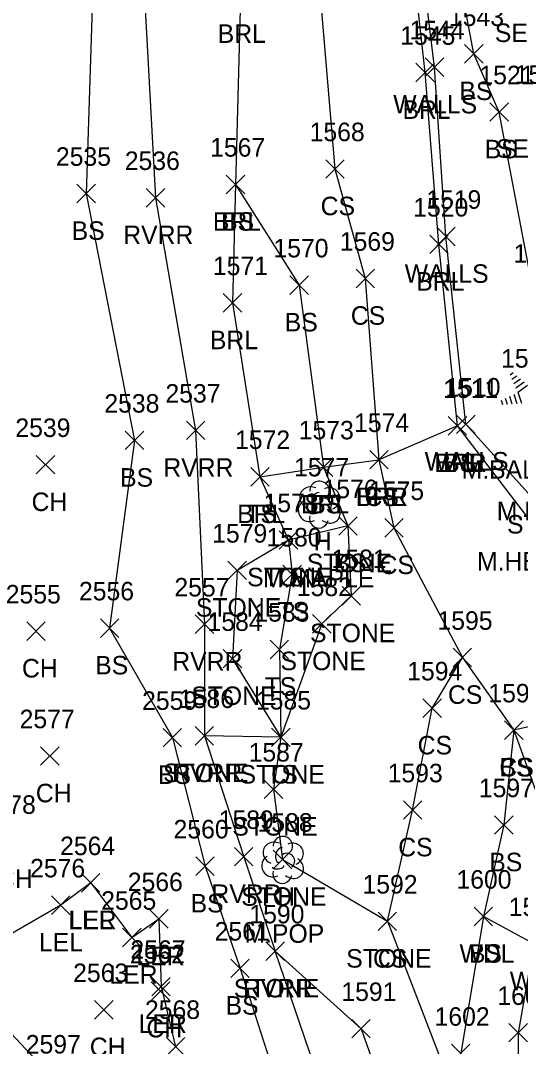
# Model space of a CAD drawing. Extents: x 1512665 to 1513714, y 110636 to 112816.
# Drawn here: x 1513047.2 to 1513101.2, y 110908.3 to 111019.1 of the extents above; entities that cross this region are included whole.
import ezdxf

# ---------------------------------------------------------------- set-up
doc = ezdxf.new("R2010")
doc.units = 0
for name, color, linetype in [('L_A', 7, 'Continuous'), ('L_C', 7, 'Continuous'), ('L_I', 7, 'Continuous'), ('L_TIC', 7, 'Continuous'), ('LABL', 7, 'Continuous'), ('LARO', 7, 'Continuous'), ('LASF', 7, 'Continuous'), ('LAWA', 7, 'Continuous'), ('LAWE', 7, 'Continuous'), ('LELB', 7, 'Continuous'), ('LTC', 7, 'Continuous'), ('LTD', 7, 'Continuous'), ('LWS', 7, 'Continuous'), ('U_A', 7, 'Continuous'), ('U_I', 7, 'Continuous')]:
    doc.layers.add(name, color=color, linetype=linetype)

msp = doc.modelspace()

# ---------------------------------------------------------------- linework, layer by layer
at = {"layer": 'L_TIC'}
for points in [[(1513095.17, 111014.48), (1513097.17, 111016.48)], [(1513097.17, 111014.48), (1513095.17, 111016.48)], [(1513089.91, 111012.45), (1513091.91, 111014.45)], [(1513091.91, 111012.45), (1513089.91, 111014.45)], [(1513090.91, 111013.04), (1513092.91, 111015.04)], [(1513092.91, 111013.04), (1513090.91, 111015.04)], [(1513097.9, 111008.19), (1513099.9, 111010.19)], [(1513099.9, 111008.19), (1513097.9, 111010.19)], [(1513080.17, 111002.04), (1513082.17, 111004.04)], [(1513082.17, 111002.04), (1513080.17, 111004.04)], [(1513069.42, 111000.37), (1513071.42, 111002.37)], [(1513071.42, 111000.37), (1513069.42, 111002.37)], [(1513069.42, 111000.37), (1513071.42, 111002.37)], [(1513071.42, 111000.37), (1513069.42, 111002.37)], [(1513053.28, 110999.38), (1513055.28, 111001.38)], [(1513055.28, 110999.38), (1513053.28, 111001.38)], [(1513060.78, 110998.93), (1513062.78, 111000.93)], [(1513062.78, 110998.93), (1513060.78, 111000.93)], [(1513092.16, 110994.74), (1513094.16, 110996.74)], [(1513094.16, 110994.74), (1513092.16, 110996.74)], [(1513091.4, 110993.9), (1513093.4, 110995.9)], [(1513093.4, 110993.9), (1513091.4, 110995.9)], [(1513083.44, 110990.21), (1513085.44, 110992.21)], [(1513085.44, 110990.21), (1513083.44, 110992.21)], [(1513076.29, 110989.49), (1513078.29, 110991.49)], [(1513078.29, 110989.49), (1513076.29, 110991.49)], [(1513069.1, 110987.57), (1513071.1, 110989.57)], [(1513071.1, 110987.57), (1513069.1, 110989.57)], [(1513094.31, 110974.46), (1513096.31, 110976.46)], [(1513096.31, 110974.46), (1513094.31, 110976.46)], [(1513065.11, 110973.8), (1513067.11, 110975.8)], [(1513067.11, 110973.8), (1513065.11, 110975.8)], [(1513093.41, 110974.3), (1513095.41, 110976.3)], [(1513095.41, 110974.3), (1513093.41, 110976.3)], [(1513093.41, 110974.3), (1513095.41, 110976.3)], [(1513095.41, 110974.3), (1513093.41, 110976.3)], [(1513093.41, 110974.3), (1513095.41, 110976.3)], [(1513095.41, 110974.3), (1513093.41, 110976.3)], [(1513058.51, 110972.72), (1513060.51, 110974.72)], [(1513060.51, 110972.72), (1513058.51, 110974.72)], [(1513048.9, 110970.09), (1513050.9, 110972.09)], [(1513050.9, 110970.09), (1513048.9, 110972.09)], [(1513084.92, 110970.63), (1513086.92, 110972.63)], [(1513086.92, 110970.63), (1513084.92, 110972.63)], [(1513084.92, 110970.63), (1513086.92, 110972.63)], [(1513086.92, 110970.63), (1513084.92, 110972.63)], [(1513084.92, 110970.63), (1513086.92, 110972.63)], [(1513086.92, 110970.63), (1513084.92, 110972.63)], [(1513078.94, 110969.83), (1513080.94, 110971.83)], [(1513080.94, 110969.83), (1513078.94, 110971.83)], [(1513078.94, 110969.83), (1513080.94, 110971.83)], [(1513080.94, 110969.83), (1513078.94, 110971.83)], [(1513072.06, 110968.79), (1513074.06, 110970.79)], [(1513074.06, 110968.79), (1513072.06, 110970.79)], [(1513072.06, 110968.79), (1513074.06, 110970.79)], [(1513074.06, 110968.79), (1513072.06, 110970.79)], [(1513081.57, 110963.48), (1513083.57, 110965.48)], [(1513083.57, 110963.48), (1513081.57, 110965.48)], [(1513081.57, 110963.48), (1513083.57, 110965.48)], [(1513083.57, 110963.48), (1513081.57, 110965.48)], [(1513081.57, 110963.48), (1513083.57, 110965.48)], [(1513083.57, 110963.48), (1513081.57, 110965.48)], [(1513086.54, 110963.28), (1513088.54, 110965.28)], [(1513088.54, 110963.28), (1513086.54, 110965.28)], [(1513075.14, 110961.96), (1513077.14, 110963.96)], [(1513077.14, 110961.96), (1513075.14, 110963.96)], [(1513075.14, 110961.96), (1513077.14, 110963.96)], [(1513077.14, 110961.96), (1513075.14, 110963.96)], [(1513069.6, 110958.68), (1513071.6, 110960.68)], [(1513071.6, 110958.68), (1513069.6, 110960.68)], [(1513075.55, 110958.26), (1513077.55, 110960.26)], [(1513077.55, 110958.26), (1513075.55, 110960.26)], [(1513081.93, 110955.92), (1513083.93, 110957.92)], [(1513083.93, 110955.92), (1513081.93, 110957.92)], [(1513055.82, 110952.44), (1513057.82, 110954.44)], [(1513057.82, 110952.44), (1513055.82, 110954.44)], [(1513066.08, 110952.86), (1513068.08, 110954.86)], [(1513068.08, 110952.86), (1513066.08, 110954.86)], [(1513078.74, 110952.9), (1513080.74, 110954.9)], [(1513080.74, 110952.9), (1513078.74, 110954.9)], [(1513047.86, 110952.11), (1513049.86, 110954.11)], [(1513049.86, 110952.11), (1513047.86, 110954.11)], [(1513074.16, 110950.14), (1513076.16, 110952.14)], [(1513076.16, 110950.14), (1513074.16, 110952.14)], [(1513069.1, 110949.14), (1513071.1, 110951.14)], [(1513071.1, 110949.14), (1513069.1, 110951.14)], [(1513093.93, 110949.26), (1513095.93, 110951.26)], [(1513095.93, 110949.26), (1513093.93, 110951.26)], [(1513093.93, 110949.26), (1513095.93, 110951.26)], [(1513095.93, 110949.26), (1513093.93, 110951.26)], [(1513090.66, 110943.8), (1513092.66, 110945.8)], [(1513092.66, 110943.8), (1513090.66, 110945.8)], [(1513099.49, 110941.42), (1513101.49, 110943.42)], [(1513101.49, 110941.42), (1513099.49, 110943.42)], [(1513099.49, 110941.42), (1513101.49, 110943.42)], [(1513101.49, 110941.42), (1513099.49, 110943.42)], [(1513062.6, 110940.61), (1513064.6, 110942.61)], [(1513064.6, 110940.61), (1513062.6, 110942.61)], [(1513066.06, 110940.81), (1513068.06, 110942.81)], [(1513068.06, 110940.81), (1513066.06, 110942.81)], [(1513066.06, 110940.81), (1513068.06, 110942.81)], [(1513068.06, 110940.81), (1513066.06, 110942.81)], [(1513074.32, 110940.65), (1513076.32, 110942.65)], [(1513076.32, 110940.65), (1513074.32, 110942.65)], [(1513074.32, 110940.65), (1513076.32, 110942.65)], [(1513076.32, 110940.65), (1513074.32, 110942.65)], [(1513074.32, 110940.65), (1513076.32, 110942.65)], [(1513076.32, 110940.65), (1513074.32, 110942.65)], [(1513049.36, 110938.63), (1513051.36, 110940.63)], [(1513051.36, 110938.63), (1513049.36, 110940.63)], [(1513073.53, 110935.03), (1513075.53, 110937.03)], [(1513075.53, 110935.03), (1513073.53, 110937.03)], [(1513088.56, 110932.79), (1513090.56, 110934.79)], [(1513090.56, 110932.79), (1513088.56, 110934.79)], [(1513098.4, 110931.18), (1513100.4, 110933.18)], [(1513100.4, 110931.18), (1513098.4, 110933.18)], [(1513070.31, 110927.75), (1513072.31, 110929.75)], [(1513072.31, 110927.75), (1513070.31, 110929.75)], [(1513074.49, 110927.45), (1513076.49, 110929.45)], [(1513076.49, 110927.45), (1513074.49, 110929.45)], [(1513066.13, 110926.73), (1513068.13, 110928.73)], [(1513068.13, 110926.73), (1513066.13, 110928.73)], [(1513053.78, 110924.92), (1513055.78, 110926.92)], [(1513055.78, 110924.92), (1513053.78, 110926.92)], [(1513053.78, 110924.92), (1513055.78, 110926.92)], [(1513055.78, 110924.92), (1513053.78, 110926.92)], [(1513050.54, 110922.52), (1513052.54, 110924.52)], [(1513052.54, 110922.52), (1513050.54, 110924.52)], [(1513096.2, 110921.3), (1513098.2, 110923.3)], [(1513098.2, 110921.3), (1513096.2, 110923.3)], [(1513096.2, 110921.3), (1513098.2, 110923.3)], [(1513098.2, 110921.3), (1513096.2, 110923.3)], [(1513061.14, 110921.03), (1513063.14, 110923.03)], [(1513063.14, 110921.03), (1513061.14, 110923.03)], [(1513085.83, 110920.77), (1513087.83, 110922.77)], [(1513087.83, 110920.77), (1513085.83, 110922.77)], [(1513085.83, 110920.77), (1513087.83, 110922.77)], [(1513087.83, 110920.77), (1513085.83, 110922.77)], [(1513058.22, 110919.02), (1513060.22, 110921.02)], [(1513060.22, 110919.02), (1513058.22, 110921.02)], [(1513073.7, 110917.55), (1513075.7, 110919.55)], [(1513075.7, 110917.55), (1513073.7, 110919.55)], [(1513073.7, 110917.55), (1513075.7, 110919.55)], [(1513075.7, 110917.55), (1513073.7, 110919.55)], [(1513069.91, 110915.69), (1513071.91, 110917.69)], [(1513071.91, 110915.69), (1513069.91, 110917.69)], [(1513061.38, 110913.72), (1513063.38, 110915.72)], [(1513063.38, 110913.72), (1513061.38, 110915.72)], [(1513061.32, 110913.23), (1513063.32, 110915.23)], [(1513063.32, 110913.23), (1513061.32, 110915.23)], [(1513055.19, 110911.21), (1513057.19, 110913.21)], [(1513057.19, 110911.21), (1513055.19, 110913.21)], [(1513082.98, 110909.17), (1513084.98, 110911.17)], [(1513084.98, 110909.17), (1513082.98, 110911.17)], [(1513099.96, 110908.74), (1513101.96, 110910.74)], [(1513101.96, 110908.74), (1513099.96, 110910.74)], [(1513062.95, 110907.23), (1513064.95, 110909.23)], [(1513064.95, 110907.23), (1513062.95, 110909.23)], [(1513093.75, 110906.49), (1513095.75, 110908.49)], [(1513095.75, 110906.49), (1513093.75, 110908.49)]]:
    msp.add_lwpolyline(points, dxfattribs=at)
at = {"layer": 'LABL'}
for points in [[(1513064.74, 111092.42), (1513066.32, 111068.68), (1513068.89, 111044.12), (1513073.88, 111036.11), (1513070.96, 111021.66), (1513070.42, 111001.37), (1513070.1, 110988.57), (1513073.06, 110969.79), (1513079.94, 110970.83), (1513085.92, 110971.63)], [(1513094.41, 110975.3), (1513092.4, 110994.9), (1513090.91, 111013.45), (1513089.22, 111028.74), (1513088.99, 111045.52), (1513085.19, 111066.71), (1513081.72, 111090.58)], [(1513094.41, 110975.3), (1513085.92, 110971.63)]]:
    msp.add_lwpolyline(points, dxfattribs=at)
at = {"layer": 'LARO'}
for points in [[(1513054.78, 110925.92), (1513051.54, 110923.52), (1513042.37, 110918.21), (1513037.26, 110919.75), (1513038.86, 110910.1), (1513036.11, 110906.18), (1513030.6, 110898.71), (1513032.35, 110888.01), (1513034.03, 110875.07), (1513033.74, 110859.16), (1513040, 110853.34), (1513041.84, 110847.28), (1513041.35, 110841.63), (1513042.36, 110832.47), (1513042.54, 110822.43), (1513049.44, 110822.77)], [(1513054.78, 110925.92), (1513059.22, 110920.02), (1513062.14, 110922.03), (1513062.38, 110914.72), (1513063.95, 110908.23)]]:
    msp.add_lwpolyline(points, dxfattribs=at)
at = {"layer": 'LASF'}
for points in [[(1513082.57, 110964.48), (1513076.14, 110962.96), (1513070.6, 110959.68), (1513070.1, 110950.14), (1513075.32, 110941.65), (1513067.06, 110941.81)], [(1513082.57, 110964.48), (1513082.93, 110956.92), (1513079.74, 110953.9), (1513075.32, 110941.65), (1513074.53, 110936.03), (1513075.49, 110928.45), (1513086.83, 110921.77), (1513094.45, 110902.07), (1513100.96, 110887.48), (1513100.96, 110871.59), (1513098.85, 110849.42), (1513096.99, 110839.11)], [(1513074.7, 110918.55), (1513083.98, 110910.17), (1513088.8, 110896.62), (1513091.57, 110886.16), (1513091.54, 110868.21), (1513090.42, 110850.25), (1513096.99, 110839.11)]]:
    msp.add_lwpolyline(points, dxfattribs=at)
at = {"layer": 'LAWA'}
msp.add_lwpolyline([(1513113.58, 110922.99), (1513102.64, 110919.33), (1513097.2, 110922.3), (1513094.75, 110907.49), (1513094.45, 110902.07), (1513096.37, 110887.11), (1513095.69, 110871.35), (1513094.56, 110849.81), (1513096.99, 110839.11), (1513095.31, 110829.26)], dxfattribs=at)
at = {"layer": 'LAWE'}
for points in [[(1513057.55, 111092.59), (1513057.76, 111063.78), (1513059.89, 111034.15), (1513061.78, 110999.93), (1513066.11, 110974.8), (1513067.08, 110953.86)], [(1513067.08, 110953.86), (1513067.06, 110941.81)], [(1513067.06, 110941.81), (1513071.31, 110928.75), (1513074.7, 110918.55)], [(1513081.14, 110899.64), (1513074.7, 110918.55)]]:
    msp.add_lwpolyline(points, dxfattribs=at)
at = {"layer": 'LELB'}
for points in [[(1513050.57, 111091.96), (1513051.2, 111062.89), (1513055.33, 111032.78), (1513054.28, 111000.38), (1513059.51, 110973.72), (1513056.82, 110953.44), (1513063.6, 110941.61), (1513067.13, 110927.73), (1513070.91, 110916.69), (1513076.1, 110900.54), (1513074.96, 110895.68), (1513079.69, 110884.14), (1513081.25, 110868.38), (1513078.34, 110857.81), (1513080.52, 110848.08), (1513078.46, 110838.38), (1513078.11, 110823.81), (1513078.51, 110819.27), (1513078.06, 110816.05), (1513076.99, 110814.7), (1513073.49, 110811.48), (1513073.8, 110795.94), (1513074.51, 110793.14), (1513077.43, 110790.98)], [(1513074.29, 111090.89), (1513073.46, 111069.86), (1513077.06, 111044.99), (1513079.13, 111026.94), (1513081.17, 111003.04), (1513084.44, 110991.21), (1513085.92, 110971.63), (1513087.54, 110964.28), (1513094.93, 110950.26), (1513100.49, 110942.42), (1513104.75, 110930.66), (1513102.64, 110919.33), (1513100.96, 110909.74), (1513100.96, 110887.48)], [(1512999.92, 111089.04), (1513004.14, 111053.62), (1513005.26, 111016.8), (1513012.57, 110991.14), (1513021.16, 110966.86), (1513021.14, 110942.53), (1513029.13, 110937.33), (1513035.68, 110924.63), (1513037.26, 110919.75), (1513042.36, 110913.68), (1513051.02, 110904.49)], [(1513105.19, 110981.77), (1513102.58, 110989.9), (1513098.9, 111009.19), (1513096.17, 111015.48), (1513093.49, 111029.55), (1513095.06, 111040.19), (1513092.91, 111045.41), (1513085.19, 111066.71)], [(1513070.42, 111001.37), (1513077.29, 110990.49), (1513079.94, 110970.83), (1513082.57, 110964.48)], [(1513156.28, 110981.33), (1513147.68, 110975.84), (1513130.86, 110966.12), (1513127.37, 110963.56), (1513113.24, 110946.25), (1513110.3, 110944.6), (1513100.49, 110942.42), (1513099.4, 110932.18), (1513097.2, 110922.3)], [(1513110.3, 110944.6), (1513109.33, 110955.26), (1513103.86, 110962.94), (1513094.41, 110975.3)], [(1513073.06, 110969.79), (1513076.14, 110962.96), (1513076.55, 110959.26), (1513075.16, 110951.14), (1513075.32, 110941.65)], [(1513086.83, 110921.77), (1513089.56, 110933.79), (1513091.66, 110944.8), (1513094.93, 110950.26)]]:
    msp.add_lwpolyline(points, dxfattribs=at)
at = {"layer": 'LTC'}
for p, q in [((1513100.08, 110980.79), (1513100.43, 110981.04)), ((1513100.29, 110980.32), (1513100.82, 110980.7)), ((1513100.5, 110979.85), (1513101.2, 110980.37)), ((1513100.71, 110979.39), (1513101.59, 110980.03)), ((1513100.48, 110978.71), (1513100.81, 110977.7)), ((1513100.93, 110978.93), (1513101.95, 110979.67)), ((1513100.93, 110978.93), (1513101.32, 110977.74)), ((1513099.11, 110978.07), (1513099.26, 110977.6)), ((1513099.57, 110978.28), (1513099.78, 110977.63)), ((1513100.02, 110978.5), (1513100.29, 110977.66))]:
    msp.add_line(p, q, dxfattribs=at)
at = {"layer": 'LTD'}
for p, q in [((1513079.45, 110966.83), (1513079.45, 110966.83)), ((1513079.45, 110966.83), (1513079.45, 110966.83)), ((1513075.49, 110928.45), (1513075.49, 110928.45)), ((1513075.49, 110928.45), (1513075.49, 110928.45))]:
    msp.add_line(p, q, dxfattribs=at)
for centre in [(1513079.49, 110968.26), (1513075.54, 110929.89)]:
    msp.add_arc(centre, 1.05, 335.5272, 180.9563, dxfattribs=at)
for centre, major_axis, ratio, start_param, end_param in [((1513078.66, 110967.5), (1.21, -0.51), 0.895232, 1.570796, 4.712389), ((1513080.49, 110967.41), (-1.14, -0.48), 0.949671, 1.570796, 4.712389), ((1513079.24, 110967.29), (-0.208, -0.792), 0.645439, 3.141593, 6.283185), ((1513079.95, 110966.66), (-0.5, 0.667), 0.989748, 3.141593, 6.283185), ((1513078.36, 110966.12), (0.58, -1.04), 0.959034, 3.141593, 6.283185), ((1513080.45, 110966), (-1.09, 0.79), 0.841452, 1.570796, 4.712389), ((1513079.45, 110965.33), (0.26, 1.06), 0.942809, 1.570796, 4.712389), ((1513078.99, 110966.08), (-0.625, -0.083), 0.423636, 0, 3.141593), ((1513074.7, 110929.12), (1.21, -0.51), 0.895232, 1.570796, 4.712389), ((1513076.53, 110929.04), (-1.14, -0.48), 0.949671, 1.570796, 4.712389), ((1513074.41, 110927.74), (0.58, -1.04), 0.959034, 3.141593, 6.283185), ((1513075.28, 110928.91), (-0.208, -0.792), 0.645439, 3.141593, 6.283185), ((1513075.99, 110928.29), (-0.5, 0.667), 0.989748, 3.141593, 6.283185), ((1513075.03, 110927.7), (-0.625, -0.083), 0.423636, 0, 3.141593), ((1513076.49, 110927.62), (-1.09, 0.79), 0.841452, 1.570796, 4.712389), ((1513075.49, 110926.95), (0.26, 1.06), 0.942809, 1.570796, 4.712389)]:
    msp.add_ellipse(centre, major_axis=major_axis, ratio=ratio, start_param=start_param, end_param=end_param, dxfattribs=at)
at = {"layer": 'LWS'}
msp.add_lwpolyline([(1513113.24, 110946.25), (1513110.87, 110954.65), (1513106.11, 110963.52), (1513095.31, 110975.46), (1513093.16, 110995.74), (1513091.91, 111014.04), (1513090.12, 111028.87), (1513090.53, 111044.09)], dxfattribs=at)

# ---------------------------------------------------------------- texts
at = {"layer": 'L_A'}
for s, p in [('BRL', (1513068.5, 111016.66)), ('BS', (1513094.61, 111010.48)), ('WALLS', (1513087.46, 111009.04)), ('BRL', (1513088.46, 111008.45)), ('BS', (1513097.34, 111004.19)), ('CS', (1513079.62, 110998.04)), ('BRL', (1513067.97, 110996.37)), ('BS', (1513068.86, 110996.37)), ('BS', (1513052.72, 110995.38)), ('RVRR', (1513058.29, 110994.93)), ('WALLS', (1513088.7, 110990.74)), ('BRL', (1513089.94, 110989.9)), ('BS', (1513075.74, 110985.49)), ('CS', (1513082.88, 110986.21)), ('BRL', (1513067.65, 110983.57)), ('WALLS', (1513090.86, 110970.46)), ('BRR', (1513091.9, 110970.3)), ('BRL', (1513091.95, 110970.3)), ('BS', (1513092.85, 110970.3)), ('RVRR', (1513062.62, 110969.8)), ('BS', (1513057.95, 110968.72)), ('CH', (1513048.39, 110966.09)), ('BRL', (1513077.48, 110965.83)), ('BS', (1513078.38, 110965.83)), ('BRR', (1513083.41, 110966.63)), ('BRL', (1513083.46, 110966.63)), ('CS', (1513084.36, 110966.63)), ('BRL', (1513070.6, 110964.79)), ('TS', (1513071.47, 110964.79)), ('STUMP', (1513099.75, 110963.66)), ('H', (1513078.88, 110961.83)), ('STONE', (1513078.12, 110959.48)), ('STONE', (1513078.12, 110959.48)), ('BS', (1513081.01, 110959.48)), ('CS', (1513085.98, 110959.28)), ('STONE', (1513071.68, 110957.96)), ('TS', (1513074.55, 110957.96)), ('STONE', (1513066.14, 110954.68)), ('TS', (1513074.96, 110954.26)), ('STONE', (1513078.47, 110951.92)), ('CH', (1513047.35, 110948.11)), ('BS', (1513055.26, 110948.44)), ('RVRR', (1513063.59, 110948.86)), ('STONE', (1513075.28, 110948.9)), ('TS', (1513073.57, 110946.14)), ('STONE', (1513065.64, 110945.14)), ('CS', (1513093.37, 110945.26)), ('CS', (1513093.37, 110945.26)), ('CS', (1513090.1, 110939.8)), ('STONE', (1513062.6, 110936.81)), ('RVRR', (1513063.57, 110936.81)), ('CS', (1513098.93, 110937.42)), ('BS', (1513098.93, 110937.42)), ('BS', (1513062.04, 110936.61)), ('STONE', (1513070.86, 110936.65)), ('STONE', (1513070.86, 110936.65)), ('TS', (1513073.73, 110936.65)), ('CH', (1513048.85, 110934.63)), ('STONE', (1513070.08, 110931.03)), ('CS', (1513088, 110928.79)), ('BS', (1513097.84, 110927.18)), ('CH', (1513044.65, 110925.38)), ('RVRR', (1513067.82, 110923.75)), ('STONE', (1513071.04, 110923.45)), ('H', (1513074.93, 110923.45)), ('BS', (1513065.57, 110922.73)), ('LER', (1513052.36, 110920.92)), ('LEL', (1513052.42, 110920.92)), ('LEL', (1513049.18, 110918.52)), ('LER', (1513059.72, 110917.03)), ('WDL', (1513094.62, 110917.3)), ('BS', (1513095.64, 110917.3)), ('STONE', (1513082.38, 110916.77)), ('CS', (1513085.27, 110916.77)), ('LER', (1513056.8, 110915.02)), ('STONE', (1513070.24, 110913.55)), ('RVRR', (1513071.21, 110913.55)), ('WDL', (1513100.05, 110914.33)), ('BS', (1513069.35, 110911.69)), ('LER', (1513059.96, 110909.72)), ('CH', (1513060.8, 110909.23)), ('CH', (1513054.68, 110907.21))]:
    msp.add_text(s, height=2, dxfattribs=at).set_placement(p)
at = {"layer": 'L_C'}
for s, p in [('M.BALSAM', (1513094.85, 110969.58)), ('M.BALSAM', (1513098.65, 110965.1)), ('M.HEMLOCK', (1513096.51, 110959.66)), ('M.MAPLE', (1513073.38, 110957.83)), ('M.POP', (1513071.39, 110919.45))]:
    msp.add_text(s, height=2, dxfattribs=at).set_placement(p)
at = {"layer": 'L_I'}
for s, p in [('1543', (1513093.48, 111018.48)), ('1544', (1513089.22, 111017.04)), ('1545', (1513088.22, 111016.45)), ('1521', (1513096.77, 111012.19)), ('1568', (1513078.43, 111006.04)), ('1567', (1513067.68, 111004.37)), ('1567', (1513067.68, 111004.37)), ('2535', (1513051.02, 111003.38)), ('2536', (1513058.46, 111002.93)), ('1520', (1513089.62, 110997.9)), ('1519', (1513091.03, 110998.74)), ('1570', (1513074.52, 110993.49)), ('1569', (1513081.69, 110994.21)), ('1518', (1513100.45, 110992.9)), ('1571', (1513067.98, 110991.57)), ('1509', (1513099.11, 110981.58)), ('2537', (1513062.85, 110977.8)), ('1511', (1513092.85, 110978.3)), ('1511', (1513092.85, 110978.3)), ('1511', (1513092.85, 110978.3)), ('1510', (1513093.1, 110978.46)), ('2538', (1513056.25, 110976.72)), ('1574', (1513083.23, 110974.63)), ('1574', (1513083.23, 110974.63)), ('1574', (1513083.23, 110974.63)), ('2539', (1513046.64, 110974.09)), ('1573', (1513077.25, 110973.83)), ('1573', (1513077.25, 110973.83)), ('1572', (1513070.37, 110972.79)), ('1572', (1513070.37, 110972.79)), ('1577', (1513076.75, 110969.83)), ('1576', (1513079.82, 110967.48)), ('1576', (1513079.82, 110967.48)), ('1576', (1513079.82, 110967.48)), ('1575', (1513084.85, 110967.28)), ('1578', (1513073.45, 110965.96)), ('1578', (1513073.45, 110965.96)), ('1579', (1513067.9, 110962.68)), ('1580', (1513073.77, 110962.26)), ('1581', (1513080.8, 110959.92)), ('2557', (1513063.82, 110956.86)), ('1582', (1513077.05, 110956.9)), ('2555', (1513045.6, 110956.11)), ('2556', (1513053.51, 110956.44)), ('1583', (1513072.46, 110954.14)), ('1584', (1513067.4, 110953.14)), ('1595', (1513092.24, 110953.26)), ('1595', (1513092.24, 110953.26)), ('1594', (1513088.97, 110947.8)), ('2559', (1513060.33, 110944.61)), ('1586', (1513064.31, 110944.81)), ('1586', (1513064.31, 110944.81)), ('1585', (1513072.63, 110944.65)), ('1585', (1513072.63, 110944.65)), ('1585', (1513072.63, 110944.65)), ('1596', (1513097.74, 110945.42)), ('1596', (1513097.74, 110945.42)), ('2577', (1513047.1, 110942.63)), ('1587', (1513071.84, 110939.03)), ('1593', (1513086.86, 110936.79)), ('1597', (1513096.71, 110935.18)), ('2578', (1513042.9, 110933.38)), ('1589', (1513068.61, 110931.75)), ('1588', (1513072.8, 110931.45)), ('1588', (1513072.8, 110931.45)), ('2560', (1513063.73, 110930.73)), ('2564', (1513051.47, 110928.92)), ('2564', (1513051.47, 110928.92)), ('2576', (1513048.23, 110926.52)), ('2566', (1513058.78, 110925.03)), ('1592', (1513084.14, 110924.77)), ('1592', (1513084.14, 110924.77)), ('1600', (1513094.29, 110925.3)), ('1600', (1513094.29, 110925.3)), ('2565', (1513055.91, 110923.02)), ('1599', (1513099.94, 110922.33)), ('1599', (1513099.94, 110922.33)), ('1590', (1513071.92, 110921.55)), ('1590', (1513071.92, 110921.55)), ('2561', (1513068.17, 110919.69)), ('2562', (1513059.01, 110917.23)), ('2567', (1513059.07, 110917.72)), ('2563', (1513052.88, 110915.21)), ('1591', (1513081.86, 110913.17)), ('1601', (1513098.71, 110912.74)), ('2568', (1513060.64, 110911.23)), ('1602', (1513091.93, 110910.49)), ('2597', (1513047.76, 110907.49))]:
    msp.add_text(s, height=2, dxfattribs=at).set_placement(p)
at = {"layer": 'U_A'}
for p in [(1513098.44, 111016.75), (1513098.56, 111004.25)]:
    msp.add_text('SEPTIC', height=2, dxfattribs=at).set_placement(p)
at = {"layer": 'U_I'}
msp.add_text('1522', height=2, dxfattribs=at).set_placement((1513100.58, 111012.25))

doc.saveas('drawing.dxf')
